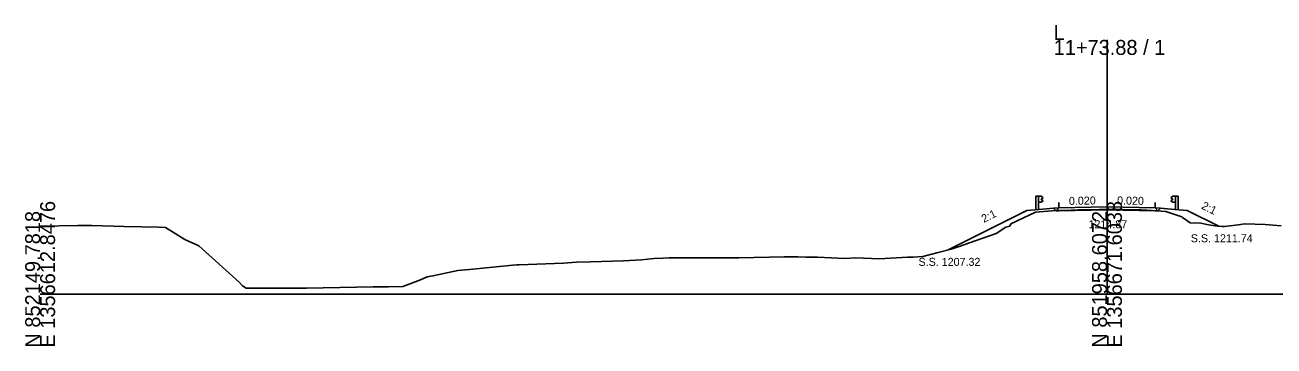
# Model space of a CAD drawing. Extents: x -26 to 3203, y -10 to 4066.
# Drawn here: x 1397.2 to 1631.3, y -9.7 to 50.4 of the extents above; entities that cross this region are included whole.
import ezdxf

# ---------------------------------------------------------------- set-up
doc = ezdxf.new("R2010")
doc.units = 0
for name, color, linetype in [('Exist Cross Section Cell', 7, 'Continuous'), ('Exist XS Center Line Elevation Label', 7, 'Continuous'), ('Exist XS Ground Line', 7, 'Continuous'), ('Prop XS Dump Level', 7, 'Continuous'), ('Prop XS Earthwork Shape', 7, 'Continuous'), ('Prop XS EOT Tick Mark', 7, 'Continuous'), ('Prop XS Finish Grade', 7, 'Continuous'), ('Prop XS Finish Grade Earthwork', 7, 'Continuous'), ('Prop XS Finish Grade Pavement', 7, 'Continuous'), ('Prop XS Guardrail', 7, 'Continuous'), ('Prop XS Pvmt Edge Slope', 7, 'Continuous'), ('Prop XS SE Text', 7, 'Continuous'), ('Prop XS Side Slope Text', 7, 'Continuous'), ('Prop XS SS Elevation Text', 7, 'Continuous'), ('Prop XS Subgrade Earthwork', 7, 'Continuous')]:
    doc.layers.add(name, color=color, linetype=linetype)

msp = doc.modelspace()

# ---------------------------------------------------------------- linework, layer by layer
at = {"layer": 'Exist Cross Section Cell'}
for p, q in [((1600, 0), (1600, 47.64)), ((1400, 0), (1600, 0)), ((1600, 0), (1800, 0))]:
    msp.add_line(p, q, dxfattribs=at)
at = {"layer": 'Exist XS Ground Line'}
msp.add_lwpolyline([(1400, 12.76), (1407.09, 12.86), (1407.69, 12.88), (1408.59, 12.87), (1409.67, 12.85), (1415.73, 12.71), (1422.26, 12.54), (1423.51, 12.48), (1427.12, 10.28), (1429.77, 9.06), (1437.31, 2.28), (1437.94, 1.59), (1438.6, 1.12), (1449.94, 1.13), (1462.42, 1.36), (1465.31, 1.41), (1468, 1.45), (1471.3, 2.72), (1472.57, 3.29), (1473.63, 3.45), (1478.33, 4.42), (1480.49, 4.66), (1488.59, 5.45), (1489.38, 5.51), (1489.82, 5.52), (1498.14, 5.85), (1500.58, 6.01), (1503.2, 6.1), (1509.37, 6.24), (1512.75, 6.44), (1515.12, 6.67), (1516.79, 6.79), (1517.93, 6.81), (1522.91, 6.83), (1528.5, 6.81), (1530.95, 6.8), (1539.49, 7), (1540.97, 7.02), (1542.05, 7.02), (1543.57, 6.97), (1545.72, 6.94), (1550.84, 6.71), (1552.92, 6.83), (1557.26, 6.64), (1562.57, 6.92), (1563.68, 6.92), (1565.5, 7.05), (1568.34, 7.84), (1570.78, 8.47), (1572.29, 8.94), (1575.29, 9.98), (1578.17, 11), (1579.25, 11.36), (1581.06, 12.57), (1581.77, 12.78), (1581.97, 13.19), (1583.14, 13.78), (1586.61, 15.39), (1589.65, 15.65), (1591.9, 15.71), (1594.62, 15.83), (1598.58, 15.88), (1600, 15.87), (1602.99, 15.86), (1606.39, 15.83), (1610.16, 15.54), (1611.04, 15.48), (1614.02, 14.51), (1614.17, 14.4), (1615.56, 13.35), (1617.56, 13.32), (1619.04, 13.02), (1620.71, 12.77), (1621.56, 12.68), (1622.03, 12.7), (1624.59, 12.98), (1625.85, 13.19), (1629.66, 13.05), (1632.63, 12.84)], dxfattribs=at)
at = {"layer": 'Prop XS Dump Level'}
for p, q in [((1600, 16.38), (1591, 16.2)), ((1609, 16.2), (1600, 16.38))]:
    msp.add_line(p, q, dxfattribs=at)
at = {"layer": 'Prop XS Earthwork Shape'}
for points in [[(1590.42, 15.67), (1589.98, 16.11), (1588, 15.96), (1585, 15.72), (1570.21, 8.32), (1570.78, 8.47), (1572.29, 8.94), (1575.29, 9.98), (1578.17, 11), (1579.25, 11.36), (1581.06, 12.57), (1581.77, 12.78), (1581.97, 13.19), (1583.14, 13.78), (1586.61, 15.39), (1589.65, 15.65)], [(1608.56, 15.66), (1600, 15.83), (1591, 15.65), (1590.45, 15.64), (1590.42, 15.67), (1591.9, 15.71), (1594.62, 15.83), (1598.58, 15.88), (1600, 15.87), (1602.99, 15.86), (1606.39, 15.83)], [(1608.56, 15.66), (1610.16, 15.54), (1611.04, 15.48), (1614.02, 14.51), (1614.17, 14.4), (1615.56, 13.35), (1617.56, 13.32), (1619.04, 13.02), (1620.71, 12.77), (1620.94, 12.74), (1615, 15.72), (1612, 15.96), (1610.02, 16.11), (1609.55, 15.64), (1609, 15.65)]]:
    msp.add_lwpolyline(points, close=True, dxfattribs=at)
at = {"layer": 'Prop XS EOT Tick Mark'}
for p, q in [((1591, 16.2), (1591, 17.2)), ((1609, 16.2), (1609, 17.2))]:
    msp.add_line(p, q, dxfattribs=at)
at = {"layer": 'Prop XS Finish Grade'}
for p, q in [((1591, 16.2), (1589.98, 16.11)), ((1609, 16.2), (1610.02, 16.11))]:
    msp.add_line(p, q, dxfattribs=at)
at = {"layer": 'Prop XS Finish Grade Earthwork'}
for p, q in [((1585, 15.72), (1570.21, 8.32)), ((1588, 15.96), (1585, 15.72)), ((1589.98, 16.11), (1588, 15.96)), ((1610.02, 16.11), (1612, 15.96)), ((1612, 15.96), (1615, 15.72)), ((1615, 15.72), (1620.94, 12.74))]:
    msp.add_line(p, q, dxfattribs=at)
at = {"layer": 'Prop XS Finish Grade Pavement'}
for p, q in [((1591, 16.2), (1600, 16.38)), ((1600, 16.38), (1609, 16.2))]:
    msp.add_line(p, q, dxfattribs=at)
at = {"layer": 'Prop XS Guardrail'}
for p, q in [((1586.68, 18.35), (1587.18, 18.35)), ((1586.68, 15.85), (1586.68, 18.35)), ((1587.18, 18.35), (1587.68, 18.35)), ((1587.18, 18.35), (1587.18, 15.85)), ((1587.68, 17.22), (1587.18, 17.22)), ((1587.68, 18.35), (1587.97, 18.15)), ((1587.97, 18.03), (1587.68, 17.83)), ((1587.68, 17.83), (1587.68, 17.74)), ((1587.68, 17.74), (1587.97, 17.54)), ((1587.97, 17.42), (1587.68, 17.22)), ((1587.97, 18.15), (1588, 18.09)), ((1588, 18.09), (1587.97, 18.03)), ((1587.97, 17.54), (1588, 17.48)), ((1588, 17.48), (1587.97, 17.42)), ((1612.03, 18.15), (1612, 18.09)), ((1612, 18.09), (1612.03, 18.03)), ((1612.03, 17.54), (1612, 17.48)), ((1612, 17.48), (1612.03, 17.42)), ((1612.32, 18.35), (1612.03, 18.15)), ((1612.03, 18.03), (1612.32, 17.83)), ((1612.32, 17.74), (1612.03, 17.54)), ((1612.03, 17.42), (1612.32, 17.22)), ((1612.82, 18.35), (1612.32, 18.35)), ((1612.32, 17.83), (1612.32, 17.74)), ((1612.32, 17.22), (1612.82, 17.22)), ((1613.32, 18.35), (1612.82, 18.35)), ((1612.82, 18.35), (1612.82, 15.85)), ((1613.32, 15.85), (1613.32, 18.35))]:
    msp.add_line(p, q, dxfattribs=at)
at = {"layer": 'Prop XS Pvmt Edge Slope'}
for p, q in [((1591, 16.2), (1590.45, 15.64)), ((1609, 16.2), (1609.55, 15.64))]:
    msp.add_line(p, q, dxfattribs=at)
at = {"layer": 'Prop XS Subgrade Earthwork'}
for p, q in [((1590.45, 15.64), (1589.98, 16.11)), ((1591, 15.65), (1590.45, 15.64)), ((1600, 15.83), (1591, 15.65)), ((1609, 15.65), (1600, 15.83)), ((1609, 15.65), (1609.55, 15.64)), ((1609.55, 15.64), (1610.02, 16.11))]:
    msp.add_line(p, q, dxfattribs=at)

# ---------------------------------------------------------------- texts
at = {"layer": 'Exist Cross Section Cell'}
for s, p in [('L', (1590, 47.64)), ('11+73.88 / 1', (1590, 44.84))]:
    msp.add_text(s, height=2.8, dxfattribs=at).set_placement(p)
for s, p in [('E 1356612.8476', (1402.8, -10)), ('E 1356671.6038', (1602.8, -10)), ('N 852149.7818', (1400, -10)), ('N 851958.6072', (1600, -10))]:
    msp.add_text(s, height=2.8, rotation=90, dxfattribs=at).set_placement(p)
at = {"layer": 'Exist XS Center Line Elevation Label'}
msp.add_text('1214.87', height=1.5, dxfattribs=at).set_placement((1596.54, 12.37))
at = {"layer": 'Prop XS Dump Level'}
for p in [(1588, 15.92), (1612, 15.92)]:
    msp.add_text('Case1', height=0.04, dxfattribs=at).set_placement(p)
at = {"layer": 'Prop XS SE Text'}
for rotation, p in [(1.1458, (1592.88, 16.73)), (358.8542, (1601.88, 16.84))]:
    msp.add_text('0.020', height=1.5, rotation=rotation, dxfattribs=at).set_placement(p)
at = {"layer": 'Prop XS Side Slope Text'}
for rotation, p in [(333.4349, (1617.58, 16.1)), (26.5651, (1576.93, 13.36))]:
    msp.add_text('2:1', height=1.5, rotation=rotation, dxfattribs=at).set_placement(p)
at = {"layer": 'Prop XS SS Elevation Text'}
for s, p in [('S.S. 1211.74', (1615.71, 9.74)), ('S.S. 1207.32', (1564.67, 5.32))]:
    msp.add_text(s, height=1.5, dxfattribs=at).set_placement(p)

doc.saveas('drawing.dxf')
